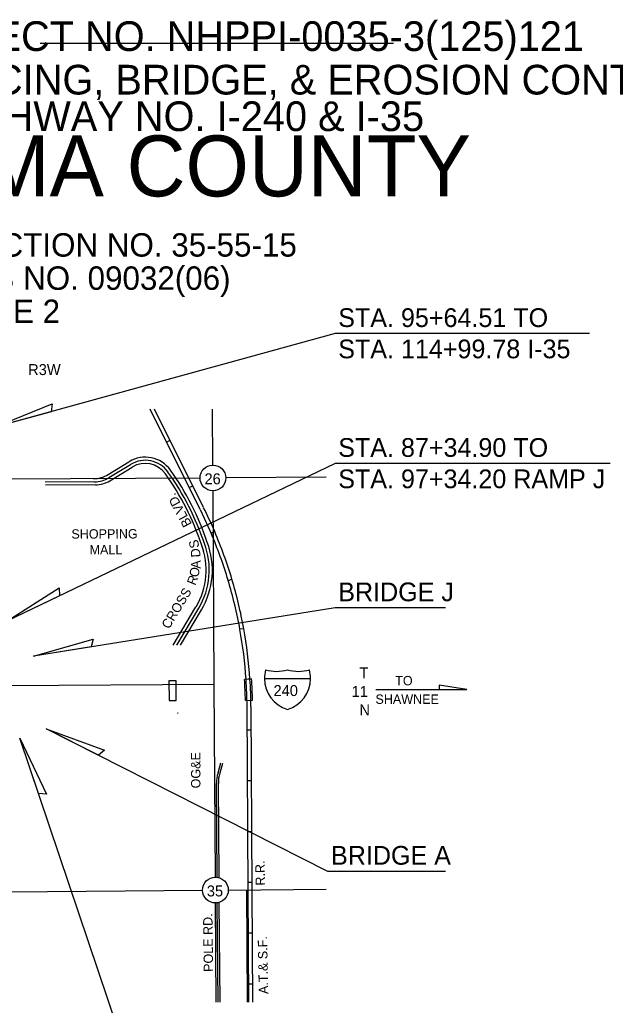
# Model space of a CAD drawing. Extents: x 2121385 to 2181200, y 132498 to 161273.
# Drawn here: x 2151083 to 2158702, y 138905 to 151519 of the extents above; entities that cross this region are included whole.
import ezdxf

# ---------------------------------------------------------------- set-up
doc = ezdxf.new("R2010")
doc.units = 0
for name, color, linetype in [('4', 7, 'Continuous'), ('5', 7, 'Continuous'), ('7', 7, 'Continuous'), ('Default', 7, 'Continuous'), ('ex-roads', 7, 'Continuous'), ('SEC', 7, 'Continuous'), ('SHT_Standard_Sheet_Txt', 7, 'Continuous'), ('TOPO_Concrete', 7, 'Continuous')]:
    doc.layers.add(name, color=color, linetype=linetype)

msp = doc.modelspace()

# ---------------------------------------------------------------- linework, layer by layer
at = {"layer": '5'}
msp.add_line((2155640, 142948), (2156447, 142948), dxfattribs=at)
for points in [[(2158370, 147501), (2155118, 147501), (2150761, 146303)], [(2158636, 145838), (2155118, 145838), (2150917, 143820)], [(2156532, 143991), (2155118, 143991), (2151258, 143375)], [(2156532, 140619), (2155025, 140619), (2151423, 142443)], [(2156215, 138224), (2152466, 138224), (2151084, 142325)]]:
    msp.add_lwpolyline(points, dxfattribs=at)
for points in [[(2150761, 146303), (2151497, 146603), (2151484, 146501)], [(2150917, 143820), (2151588, 144247), (2151593, 144145)], [(2151258, 143375), (2152023, 143592), (2151999, 143493)], [(2156805, 142948), (2156449, 143001), (2156447, 142948)], [(2151423, 142443), (2152170, 142170), (2152092, 142104)], [(2151084, 142325), (2151426, 141607), (2151324, 141615)]]:
    msp.add_lwpolyline(points, close=True, dxfattribs=at)
for centre in [(2153555, 145654), (2153587, 140379)]:
    msp.add_circle(centre, 165, dxfattribs=at)
at = {"layer": '7'}
msp.add_line((2154214, 143086), (2154804, 143086), dxfattribs=at)
for centre, radius, start, end in [((2154628, 143089), 414, 164.7751, 180.4819), ((2154370, 143723), 544, 254.9134, 284.7677), ((2154648, 143723), 544, 255.2323, 285.0866), ((2154390, 143089), 414, 359.5181, 15.2249), ((2154628, 143089), 414, 180.4819, 253.3156), ((2154390, 143089), 414, 286.6844, 359.5181)]:
    msp.add_arc(centre, radius, start, end, dxfattribs=at)
at = {"layer": 'Default'}
for p, q in [((2154214, 143086), (2154509, 143087)), ((2154509, 143087), (2154804, 143086))]:
    msp.add_line(p, q, dxfattribs=at)
for centre, radius, start, end in [((2154628, 143089), 414, 164.7751, 180.4819), ((2154370, 143723), 544, 254.9134, 284.7677), ((2154648, 143723), 544, 255.2323, 285.0866), ((2154390, 143089), 414, 359.5181, 15.2249)]:
    msp.add_arc(centre, radius, start, end, dxfattribs=at)
at = {"layer": 'ex-roads'}
for p, q in [((2153391, 145252), (2152754, 146535)), ((2153436, 145274), (2152809, 146535)), ((2152963, 146113), (2153007, 146137)), ((2152213, 145697), (2152481, 145861)), ((2152225, 145658), (2152502, 145827)), ((2152236, 145618), (2152523, 145793)), ((2152040, 145605), (2151410, 145602)), ((2152051, 145565), (2151413, 145562)), ((2153253, 145530), (2153296, 145555)), ((2153391, 145252), (2153541, 144926)), ((2153046, 143515), (2153338, 144006)), ((2153092, 143514), (2153373, 143986)), ((2153138, 143513), (2153407, 143965)), ((2154057, 140383), (2154042, 142731)), ((2153994, 142431), (2154044, 142431)), ((2153620, 141882), (2153658, 142008)), ((2153676, 141999), (2153642, 141874)), ((2153609, 140542), (2153600, 141743)), ((2153634, 140537), (2153625, 141744)), ((2153998, 141781), (2154048, 141781)), ((2154002, 141131), (2154052, 141131)), ((2154006, 140481), (2154056, 140481)), ((2153996, 138945), (2153987, 140382)), ((2154066, 138945), (2154057, 140383)), ((2153621, 138945), (2153611, 140216)), ((2153646, 138945), (2153636, 140222)), ((2154011, 139831), (2154061, 139831)), ((2154015, 139181), (2154065, 139181))]:
    msp.add_line(p, q, dxfattribs=at)
for points in [[(2153577, 144968), (2153531, 144949)], [(2153750, 144343), (2153798, 144357)], [(2153949, 143725), (2153900, 143717)], [(2154049, 143082), (2153959, 143076)], [(2153979, 143078), (2154029, 143081)], [(2153971, 142805), (2154061, 142810)], [(2154016, 138945), (2154007, 140382), (2153992, 142731)]]:
    msp.add_lwpolyline(points, dxfattribs=at)
msp.add_lwpolyline([(2153083, 143059), (2152993, 143058), (2152994, 142806), (2153084, 142806)], close=True, dxfattribs=at)
for centre, radius, start, end in [((2152689, 145522), 398, 35.522, 121.4325), ((2152689, 145522), 358, 35.522, 121.4325), ((2152689, 145522), 318, 35.522, 121.4325), ((2150173, 143726), 3409, 18.404, 35.522), ((2150173, 143726), 3449, 18.4179, 35.522), ((2150173, 143726), 3489, 18.4312, 35.522), ((2152027, 146003), 358, 270.3312, 301.4325), ((2152038, 145963), 358, 270.3312, 301.4325), ((2152049, 145923), 358, 270.3312, 301.4325), ((2148243, 142693), 5799, 23.0955, 26.4258), ((2148243, 142693), 5749, 16.6766, 23.0987), ((2148243, 142693), 5799, 16.6733, 23.0955), ((2152550, 144476), 958, 329.2162, 20.8194), ((2152550, 144476), 998, 329.2162, 20.8194), ((2152550, 144476), 918, 329.2162, 20.8194), ((2148243, 142693), 5749, 10.2544, 16.6766), ((2148243, 142693), 5799, 10.2511, 16.6733), ((2148243, 142693), 5749, 3.8322, 10.2544), ((2148243, 142693), 5799, 3.829, 10.2511), ((2148243, 142693), 5729, 1.1123, 3.8322), ((2148243, 142693), 5749, 0.3742, 3.8322), ((2148243, 142693), 5799, 0.3742, 3.829), ((2148243, 142693), 5819, 1.1511, 3.829), ((2152536, 141636), 1159, 60.4098, 60.6793), ((2153982, 141759), 382, 161.2745, 182.3697), ((2154007, 141760), 382, 162.6975, 182.3697)]:
    msp.add_arc(centre, radius, start, end, dxfattribs=at)
at = {"layer": 'SEC'}
for p, q in [((2153554, 145819), (2153551, 146535)), ((2153390, 145653), (2150906, 145639)), ((2155005, 145663), (2153719, 145655)), ((2153570, 143016), (2153556, 145489)), ((2150922, 142997), (2153570, 143016)), ((2153586, 140544), (2153570, 143016)), ((2150945, 140359), (2153422, 140378)), ((2153752, 140380), (2155005, 140390)), ((2153596, 138945), (2153588, 140214)), ((2153591, 139759), (2153588, 140214))]:
    msp.add_line(p, q, dxfattribs=at)
at = {"layer": 'TOPO_Concrete'}
msp.add_line((2155863, 151213), (2151347, 151213), dxfattribs=at)

# ---------------------------------------------------------------- texts
at = {"layer": '4'}
for s, p in [('STA. 95+64.51 TO', (2155158, 147586)), ('STA. 114+99.78 I-35', (2155158, 147186)), ('STA. 87+34.90 TO', (2155158, 145924)), ('STA. 97+34.20 RAMP J', (2155158, 145523)), ('BRIDGE J', (2155158, 144076)), ('BRIDGE A', (2155066, 140704))]:
    msp.add_text(s, height=240, dxfattribs=at).set_placement(p)
at = {"layer": '5'}
for s, p in [('R3W', (2151191, 146971)), ('26', (2153447, 145573)), ('T', (2155429, 143089)), ('240', (2154330, 142863)), ('11', (2155329, 142852)), ('N', (2155429, 142615)), ('35', (2153477, 140298))]:
    msp.add_text(s, height=140, dxfattribs=at).set_placement(p)
at = {"layer": 'SHT_Standard_Sheet_Txt'}
for s, height, p in [('FEDERAL AID PROJECT NO. NHPPI-0035-3(125)121', 380, (2145933, 151119)), ('GRADING, DRAINAGE, SURFACING, BRIDGE, & EROSION CONTROL PLANS', 380, (2143442, 150562)), ('INTERSTATE HIGHWAY NO. I-240 & I-35', 380, (2146684, 150094)), ('OKLAHOMA COUNTY', 780, (2146249, 149258)), ('CONTROL SECTION NO. 35-55-15', 300, (2148230, 148487)), ('STATE JOB NO. 09032(06)', 300, (2148831, 148062)), ('PHASE 2', 300, (2149905, 147637))]:
    msp.add_text(s, height=height, dxfattribs=at).set_placement(p)
for s, rotation, p in [('BLVD.', 118.4907, (2153289, 145065)), ('SHOPPING', 0.188, (2151745, 144877)), ('S', 102.0665, (2153383, 144768)), ('MALL', 0.188, (2151977, 144675)), ('D', 93.3736, (2153396, 144641)), ('A', 90, (2153396, 144493)), ('O', 79.9711, (2153369, 144378)), ('R', 68.1445, (2153329, 144271)), ('CROSS', 58.9723, (2152993, 143712)), ('TO', 359.9713, (2155887, 143000)), ('SHAWNEE', 359.9713, (2155634, 142763)), ('OG&E', 90, (2153395, 141681)), ('R.R.', 91.1141, (2154222, 140438)), ('POLE RD.', 90.7449, (2153558, 139333)), ('A.T.& S.F.', 91.1141, (2154262, 139050))]:
    msp.add_text(s, height=120, rotation=rotation, dxfattribs=at).set_placement(p)

doc.saveas('drawing.dxf')
